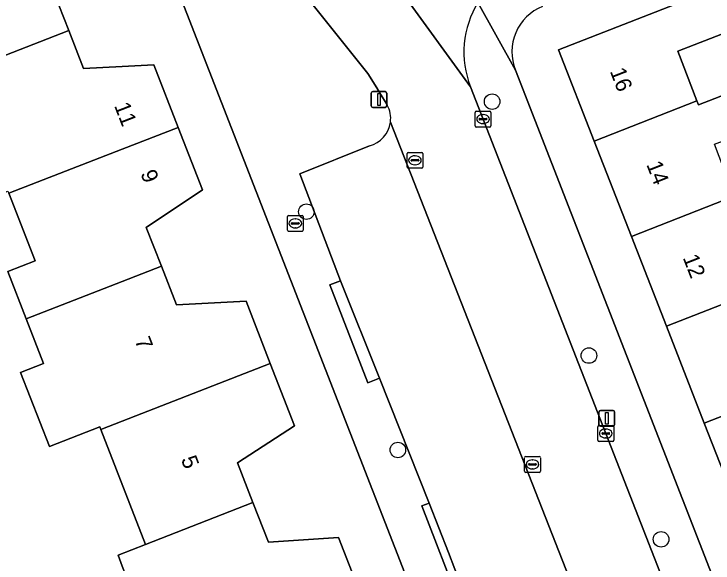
# Model space of a CAD drawing. Extents: x 159680 to 160786, y 387323 to 388340.
# Drawn here: x 159993.17 to 160037.27, y 387705.71 to 387740.35 of the extents above; entities that cross this region are included whole.
import ezdxf

# ---------------------------------------------------------------- set-up
doc = ezdxf.new("R2010")
doc.units = 0
for name, color, linetype in [('IMGEO_Boom', 7, 'Continuous'), ('IMGEO_Brandkraan', 7, 'Continuous'), ('IMGEO_Erf', 7, 'Continuous'), ('IMGEO_Kolk', 7, 'Continuous'), ('IMGEO_Lichtmast', 7, 'Continuous'), ('IMGEO_Pand', 7, 'Continuous'), ('IMGEO_Pand_nummerreeks', 7, 'Continuous'), ('IMGEO_Parkeervlak_open', 7, 'Continuous'), ('IMGEO_Rijbaan_lokaal_open', 7, 'Continuous'), ('IMGEO_Voetpad_open', 7, 'Continuous')]:
    doc.layers.add(name, color=color, linetype=linetype)

msp = doc.modelspace()

# ---------------------------------------------------------------- linework, layer by layer
at = {"layer": 'IMGEO_Boom'}
for centre in [(160023.329, 387734.817), (160011.613, 387727.875), (160029.436, 387718.799), (160017.386, 387712.847), (160033.988, 387707.208)]:
    msp.add_circle(centre, 0.489, dxfattribs=at)
at = {"layer": 'IMGEO_Brandkraan'}
for p, q in [((160010.413, 387726.709), (160010.413, 387727.561)), ((160010.488, 387727.635), (160011.34, 387727.635)), ((160010.901, 387727.415), (160010.926, 387727.415)), ((160011.414, 387727.561), (160011.414, 387726.709)), ((160010.672, 387727.129), (160010.672, 387727.141)), ((160011.11, 387727.092), (160010.712, 387727.092)), ((160010.715, 387727.178), (160011.113, 387727.178)), ((160010.924, 387726.855), (160010.899, 387726.855)), ((160011.156, 387727.141), (160011.156, 387727.129)), ((160011.34, 387726.635), (160010.488, 387726.635))]:
    msp.add_line(p, q, dxfattribs=at)
for points in [[(160010.413, 387726.709), (160010.413, 387727.561)], [(160010.488, 387727.635), (160011.34, 387727.635)], [(160011.414, 387727.561), (160011.414, 387726.709)], [(160011.34, 387726.635), (160010.488, 387726.635)]]:
    msp.add_lwpolyline(points, dxfattribs=at)
for centre, radius, start, end in [((160010.49, 387727.559), 0.0765, 91.552, 178.448), ((160010.49, 387727.559), 0.0765, 91.552, 178.448), ((160011.338, 387727.559), 0.0765, 1.552, 88.448), ((160011.338, 387727.559), 0.0765, 1.552, 88.448), ((160010.712, 387727.138), 0.0403, 85.8775, 175.7526), ((160010.709, 387727.128), 0.0366, 178.938, 274.7102), ((160011.113, 387727.135), 0.043, 264.8664, 352.4533), ((160011.117, 387727.14), 0.0386, 1.7309, 96.639), ((160010.49, 387726.711), 0.0765, 181.552, 268.448), ((160010.49, 387726.711), 0.0765, 181.552, 268.448), ((160011.338, 387726.711), 0.0765, 271.552, 358.448), ((160011.338, 387726.711), 0.0765, 271.552, 358.448)]:
    msp.add_arc(centre, radius, start, end, dxfattribs=at)
for centre, major_axis, ratio, start_param, end_param in [((160010.9, 387727.135), (-0.387, 0.002), 0.722429, 4.712389, 7.853982), ((160010.925, 387727.135), (-0.39, 0.002), 0.717154, 1.570796, 4.712389)]:
    msp.add_ellipse(centre, major_axis=major_axis, ratio=ratio, start_param=start_param, end_param=end_param, dxfattribs=at)
at = {"layer": 'IMGEO_Erf'}
for points in [[(159995.682, 387741.712), (159996.618, 387739.305), (159997.553, 387736.899), (160000, 387737.032), (160001.989, 387737.141), (160003.523, 387733.195), (160005.056, 387729.25), (160001.515, 387726.886), (160002.466, 387724.44), (160003.416, 387721.997), (160007.807, 387722.232), (160009.336, 387718.298), (160010.865, 387714.366), (160007.272, 387712.031), (160008.244, 387709.529), (160009.217, 387707.026), (160013.649, 387707.319), (160015.175, 387703.392), (160016.701, 387699.467), (160013.143, 387696.999), (160014.138, 387694.441), (160020.94, 387697.092), (160000.318, 387750)], [(159975.76, 387748.314), (159998.986, 387688.539), (160005.599, 387691.121), (160004.381, 387694.254), (160006.104, 387694.923), (160004.437, 387699.21), (160002.643, 387703.826), (160000.921, 387703.156), (160000, 387705.525), (159999.732, 387706.214), (160001.454, 387706.885), (159998.637, 387714.132), (159998.573, 387714.296), (159995.401, 387713.06), (159993.584, 387717.732), (159995.036, 387718.296), (159993.938, 387721.12), (159992.779, 387724.102), (159994.501, 387724.772), (159992.842, 387729.037)], [(160038.953, 387708.82), (160036.716, 387714.544), (160034.331, 387720.644), (160032.112, 387726.319), (160029.764, 387732.326), (160027.515, 387738.08), (160044.3, 387744.642)], [(160024.811, 387736.808), (160043.442, 387688.944)]]:
    msp.add_lwpolyline(points, dxfattribs=at)
msp.add_lwpolyline([(160040.757, 387736.624), (160039.547, 387739.743), (160035.038, 387737.994), (160036.254, 387734.86), (160036.348, 387734.617), (160040.857, 387736.366)], close=True, dxfattribs=at)
msp.add_arc((160027.649, 387737.975), 3.068, 111.9227, 202.3641, dxfattribs=at)
at = {"layer": 'IMGEO_Kolk'}
for p, q in [((160022.256, 387733.29), (160022.256, 387734.142)), ((160022.331, 387734.216), (160023.183, 387734.216)), ((160022.744, 387733.996), (160022.769, 387733.996)), ((160023.257, 387734.142), (160023.257, 387733.29)), ((160022.515, 387733.71), (160022.515, 387733.722)), ((160022.953, 387733.673), (160022.555, 387733.673)), ((160022.558, 387733.759), (160022.956, 387733.759)), ((160022.999, 387733.722), (160022.999, 387733.71)), ((160023.183, 387733.216), (160022.331, 387733.216)), ((160022.767, 387733.436), (160022.742, 387733.436)), ((160017.962, 387730.692), (160017.962, 387731.544)), ((160018.037, 387731.618), (160018.889, 387731.618)), ((160018.45, 387731.398), (160018.475, 387731.398)), ((160018.963, 387731.544), (160018.963, 387730.692)), ((160018.221, 387731.112), (160018.221, 387731.124)), ((160018.659, 387731.075), (160018.261, 387731.075)), ((160018.264, 387731.161), (160018.662, 387731.161)), ((160018.473, 387730.838), (160018.448, 387730.838)), ((160018.705, 387731.124), (160018.705, 387731.112)), ((160018.889, 387730.618), (160018.037, 387730.618)), ((160030, 387713.457), (160030, 387714.309)), ((160030.075, 387714.383), (160030.927, 387714.383)), ((160030.488, 387714.163), (160030.513, 387714.163)), ((160031.001, 387714.309), (160031.001, 387713.457)), ((160030.259, 387713.877), (160030.259, 387713.889)), ((160030.697, 387713.84), (160030.299, 387713.84)), ((160030.302, 387713.926), (160030.7, 387713.926)), ((160030.743, 387713.889), (160030.743, 387713.877)), ((160030.927, 387713.383), (160030.075, 387713.383)), ((160030.511, 387713.603), (160030.486, 387713.603)), ((160025.376, 387711.507), (160025.376, 387712.359)), ((160025.451, 387712.433), (160026.303, 387712.433)), ((160026.377, 387712.359), (160026.377, 387711.507)), ((160025.635, 387711.927), (160025.635, 387711.939)), ((160026.073, 387711.89), (160025.675, 387711.89)), ((160025.678, 387711.976), (160026.076, 387711.976)), ((160025.864, 387712.213), (160025.889, 387712.213)), ((160026.119, 387711.939), (160026.119, 387711.927)), ((160026.303, 387711.433), (160025.451, 387711.433)), ((160025.887, 387711.653), (160025.862, 387711.653))]:
    msp.add_line(p, q, dxfattribs=at)
for points in [[(160022.256, 387733.29), (160022.256, 387734.142)], [(160022.331, 387734.216), (160023.183, 387734.216)], [(160023.257, 387734.142), (160023.257, 387733.29)], [(160023.183, 387733.216), (160022.331, 387733.216)], [(160017.962, 387730.692), (160017.962, 387731.544)], [(160018.037, 387731.618), (160018.889, 387731.618)], [(160018.963, 387731.544), (160018.963, 387730.692)], [(160018.889, 387730.618), (160018.037, 387730.618)], [(160030, 387713.457), (160030, 387714.309)], [(160030.075, 387714.383), (160030.927, 387714.383)], [(160031.001, 387714.309), (160031.001, 387713.457)], [(160030.927, 387713.383), (160030.075, 387713.383)], [(160025.376, 387711.507), (160025.376, 387712.359)], [(160025.451, 387712.433), (160026.303, 387712.433)], [(160026.377, 387712.359), (160026.377, 387711.507)], [(160026.303, 387711.433), (160025.451, 387711.433)]]:
    msp.add_lwpolyline(points, dxfattribs=at)
for centre, radius, start, end in [((160022.333, 387734.14), 0.0765, 91.552, 178.448), ((160022.333, 387734.14), 0.0765, 91.552, 178.448), ((160023.181, 387734.14), 0.0765, 1.552, 88.448), ((160023.181, 387734.14), 0.0765, 1.552, 88.448), ((160022.555, 387733.719), 0.0403, 85.8775, 175.7526), ((160022.552, 387733.709), 0.0366, 178.938, 274.7102), ((160022.956, 387733.716), 0.043, 264.8664, 352.4533), ((160022.96, 387733.721), 0.0386, 1.7309, 96.639), ((160022.333, 387733.292), 0.0765, 181.552, 268.448), ((160022.333, 387733.292), 0.0765, 181.552, 268.448), ((160023.181, 387733.292), 0.0765, 271.552, 358.448), ((160023.181, 387733.292), 0.0765, 271.552, 358.448), ((160018.039, 387731.542), 0.0765, 91.552, 178.448), ((160018.039, 387731.542), 0.0765, 91.552, 178.448), ((160018.887, 387731.542), 0.0765, 1.552, 88.448), ((160018.887, 387731.542), 0.0765, 1.552, 88.448), ((160018.261, 387731.121), 0.0403, 85.8775, 175.7526), ((160018.258, 387731.111), 0.0366, 178.938, 274.7102), ((160018.662, 387731.118), 0.043, 264.8664, 352.4533), ((160018.666, 387731.123), 0.0386, 1.7309, 96.639), ((160018.039, 387730.694), 0.0765, 181.552, 268.448), ((160018.039, 387730.694), 0.0765, 181.552, 268.448), ((160018.887, 387730.694), 0.0765, 271.552, 358.448), ((160018.887, 387730.694), 0.0765, 271.552, 358.448), ((160030.077, 387714.307), 0.0765, 91.552, 178.448), ((160030.077, 387714.307), 0.0765, 91.552, 178.448), ((160030.925, 387714.307), 0.0765, 1.552, 88.448), ((160030.925, 387714.307), 0.0765, 1.552, 88.448), ((160030.299, 387713.886), 0.0403, 85.8775, 175.7526), ((160030.296, 387713.876), 0.0366, 178.938, 274.7102), ((160030.7, 387713.883), 0.043, 264.8664, 352.4533), ((160030.704, 387713.888), 0.0386, 1.7309, 96.639), ((160030.077, 387713.459), 0.0765, 181.552, 268.448), ((160030.077, 387713.459), 0.0765, 181.552, 268.448), ((160030.925, 387713.459), 0.0765, 271.552, 358.448), ((160030.925, 387713.459), 0.0765, 271.552, 358.448), ((160025.453, 387712.357), 0.0765, 91.552, 178.448), ((160025.453, 387712.357), 0.0765, 91.552, 178.448), ((160026.301, 387712.357), 0.0765, 1.552, 88.448), ((160026.301, 387712.357), 0.0765, 1.552, 88.448), ((160025.675, 387711.936), 0.0403, 85.8775, 175.7526), ((160025.672, 387711.926), 0.0366, 178.938, 274.7102), ((160026.076, 387711.933), 0.043, 264.8664, 352.4533), ((160026.08, 387711.938), 0.0386, 1.7309, 96.639), ((160025.453, 387711.509), 0.0765, 181.552, 268.448), ((160025.453, 387711.509), 0.0765, 181.552, 268.448), ((160026.301, 387711.509), 0.0765, 271.552, 358.448), ((160026.301, 387711.509), 0.0765, 271.552, 358.448)]:
    msp.add_arc(centre, radius, start, end, dxfattribs=at)
for centre, major_axis, ratio, start_param, end_param in [((160022.743, 387733.716), (-0.387, 0.002), 0.722429, 4.712389, 7.853982), ((160022.768, 387733.716), (-0.39, 0.002), 0.717154, 1.570796, 4.712389), ((160018.449, 387731.118), (-0.387, 0.002), 0.722429, 4.712389, 7.853982), ((160018.474, 387731.118), (-0.39, 0.002), 0.717154, 1.570796, 4.712389), ((160030.487, 387713.883), (-0.387, 0.002), 0.722429, 4.712389, 7.853982), ((160030.512, 387713.883), (-0.39, 0.002), 0.717154, 1.570796, 4.712389), ((160025.863, 387711.933), (-0.387, 0.002), 0.722429, 4.712389, 7.853982), ((160025.888, 387711.933), (-0.39, 0.002), 0.717154, 1.570796, 4.712389)]:
    msp.add_ellipse(centre, major_axis=major_axis, ratio=ratio, start_param=start_param, end_param=end_param, dxfattribs=at)
at = {"layer": 'IMGEO_Lichtmast'}
for p, q in [((160015.695, 387734.554), (160015.695, 387735.354)), ((160015.695, 387735.354), (160015.695, 387734.554)), ((160015.795, 387735.454), (160016.585, 387735.454)), ((160016.585, 387735.454), (160015.795, 387735.454)), ((160016.685, 387735.354), (160016.685, 387734.554)), ((160016.685, 387734.554), (160016.685, 387735.354)), ((160016.585, 387734.454), (160015.795, 387734.454)), ((160015.795, 387734.454), (160016.585, 387734.454)), ((160030.07, 387714.44), (160030.07, 387715.24)), ((160030.07, 387715.24), (160030.07, 387714.44)), ((160030.17, 387715.34), (160030.96, 387715.34)), ((160030.96, 387715.34), (160030.17, 387715.34)), ((160031.06, 387715.24), (160031.06, 387714.44)), ((160031.06, 387714.44), (160031.06, 387715.24)), ((160030.96, 387714.34), (160030.17, 387714.34)), ((160030.17, 387714.34), (160030.96, 387714.34))]:
    msp.add_line(p, q, dxfattribs=at)
for points in [[(160016.115, 387735.329), (160016.265, 387735.329), (160016.265, 387734.579), (160016.115, 387734.579), (160016.115, 387735.329)], [(160030.49, 387715.215), (160030.64, 387715.215), (160030.64, 387714.465), (160030.49, 387714.465), (160030.49, 387715.215)]]:
    msp.add_lwpolyline(points, dxfattribs=at)
for centre, start, end in [((160015.795, 387735.354), 90, 180), ((160015.795, 387735.354), 90, 180), ((160016.585, 387735.354), 0, 90), ((160016.585, 387735.354), 360, 90), ((160015.795, 387734.554), 180, 270), ((160015.795, 387734.554), 180, 270), ((160016.585, 387734.554), 270, 0), ((160016.585, 387734.554), 270, 0), ((160030.17, 387715.24), 90, 180), ((160030.17, 387715.24), 90, 180), ((160030.96, 387715.24), 0, 90), ((160030.96, 387715.24), 360, 90), ((160030.17, 387714.44), 180, 270), ((160030.17, 387714.44), 180, 270), ((160030.96, 387714.44), 270, 0), ((160030.96, 387714.44), 270, 0)]:
    msp.add_arc(centre, 0.1, start, end, dxfattribs=at)
at = {"layer": 'IMGEO_Pand'}
for points in [[(159999.229, 387744.189), (159997.708, 387748.102), (159987.045, 387743.95), (159987.004, 387744.054), (159981.993, 387742.106), (159984.024, 387736.881), (159987.314, 387738.16), (159988.086, 387736.175), (159988.151, 387736.008), (159996.618, 387739.305), (159995.682, 387741.712)], [(160046.55, 387738.886), (160044.3, 387744.642), (160027.515, 387738.08), (160029.764, 387732.326), (160036.254, 387734.86), (160035.038, 387737.994), (160039.547, 387739.743), (160040.757, 387736.624)], [(160001.989, 387737.141), (160000, 387737.032), (159997.553, 387736.899), (159996.618, 387739.305), (159988.151, 387736.008), (159988.086, 387736.175), (159986.209, 387735.446), (159989.189, 387727.78), (159992.787, 387729.178), (159992.842, 387729.037), (160000, 387731.824), (160003.523, 387733.195)], [(160040.757, 387736.624), (160040.857, 387736.366), (160036.348, 387734.617), (160036.254, 387734.86), (160029.764, 387732.326), (160032.112, 387726.319), (160038.589, 387728.848), (160037.36, 387732.135), (160041.869, 387733.821), (160043.071, 387730.603), (160048.898, 387732.879), (160046.55, 387738.886)], [(160003.523, 387733.195), (160000, 387731.824), (159992.842, 387729.037), (159994.501, 387724.772), (159992.779, 387724.102), (159993.938, 387721.12), (160000, 387723.48), (160002.466, 387724.44), (160001.515, 387726.886), (160005.056, 387729.25)], [(160032.112, 387726.319), (160034.331, 387720.644), (160040.854, 387723.191), (160039.642, 387726.278), (160044.139, 387728.043), (160045.352, 387724.953), (160051.117, 387727.204), (160048.898, 387732.879), (160043.071, 387730.603), (160043.128, 387730.452), (160038.589, 387728.848)], [(160043.229, 387717.087), (160041.962, 387720.394), (160046.457, 387722.115), (160047.71, 387718.842), (160053.501, 387721.103), (160051.117, 387727.204), (160045.352, 387724.953), (160045.482, 387724.623), (160040.985, 387722.858), (160040.854, 387723.191), (160034.331, 387720.644), (160036.716, 387714.544)], [(160007.807, 387722.232), (160003.416, 387721.997), (160002.466, 387724.44), (160000, 387723.48), (159993.938, 387721.12), (159995.036, 387718.296), (159993.584, 387717.732), (159995.401, 387713.06), (159998.573, 387714.296), (159998.637, 387714.132), (160000, 387714.663), (160009.336, 387718.298)], [(160036.716, 387714.544), (160038.953, 387708.82), (160045.504, 387711.378), (160044.265, 387714.539), (160048.719, 387716.285), (160049.959, 387713.123), (160055.739, 387715.38), (160053.501, 387721.103), (160047.71, 387718.842), (160043.229, 387717.087)], [(160009.336, 387718.298), (160000, 387714.663), (159998.637, 387714.132), (160001.454, 387706.885), (160008.244, 387709.529), (160007.272, 387712.031), (160010.865, 387714.366)], [(160008.244, 387709.529), (160001.454, 387706.885), (159999.732, 387706.214), (160000, 387705.525), (160000.921, 387703.156), (160002.643, 387703.826), (160004.437, 387699.21), (160015.175, 387703.392), (160013.649, 387707.319), (160009.217, 387707.026)]]:
    msp.add_lwpolyline(points, close=True, dxfattribs=at)
at = {"layer": 'IMGEO_Parkeervlak_open'}
for points in [[(160028.819, 387703.181), (160016.916, 387733.521)], [(160015.59, 387732.032), (160011.193, 387730.259), (160013.761, 387723.511), (160016.218, 387717.369), (160019.367, 387709.498), (160020.568, 387706.378), (160021.776, 387703.229), (160022.38, 387701.656), (160026.873, 387703.385)]]:
    msp.add_lwpolyline(points, dxfattribs=at)
msp.add_arc((160015.154, 387733.755), 1.777, 284.1895, 352.4384, dxfattribs=at)
at = {"layer": 'IMGEO_Rijbaan_lokaal_open'}
for points in [[(160021.961, 387735.751), (160013.336, 387747.64), (160008.53, 387745.755), (160008.762, 387745.396), (160011.619, 387741.451), (160015.485, 387736.6), (160016.05, 387735.681), (160016.293, 387735.286), (160016.681, 387734.654), (160016.715, 387734.598)], [(160013.336, 387747.64), (160021.961, 387735.751)], [(160029.51, 387702.449), (160034.24, 387704.299), (160021.961, 387735.751)], [(160016.916, 387733.521), (160028.819, 387703.181)]]:
    msp.add_lwpolyline(points, dxfattribs=at)
for centre, radius, start, end in [((160027.56, 387737.937), 6.01, 148.4674, 201.324), ((160015.145, 387733.748), 1.786, 352.7081, 28.4348)]:
    msp.add_arc(centre, radius, start, end, dxfattribs=at)
at = {"layer": 'IMGEO_Voetpad_open'}
for points in [[(160000.318, 387750), (160020.94, 387697.092), (160021.461, 387695.756), (160027.934, 387698.27), (160029.18, 387695.062), (160031.513, 387689.139), (160033.94, 387682.976), (160034.971, 387680.356), (160036.074, 387677.556), (160037.17, 387674.748), (160039.479, 387669.024)], [(160016.715, 387734.598), (160016.681, 387734.654), (160016.293, 387735.286), (160016.05, 387735.681), (160015.485, 387736.6), (160011.619, 387741.451)], [(160043.442, 387688.944), (160024.811, 387736.808), (160022.437, 387741.08)], [(160022.437, 387741.08), (160024.811, 387736.808)], [(160021.961, 387735.751), (160034.24, 387704.299), (160035.472, 387701.152), (160040.216, 387689.036), (160041.193, 387689.419), (160042.373, 387686.406), (160042.561, 387685.927), (160041.583, 387685.544), (160046.561, 387672.828)], [(160026.873, 387703.385), (160022.38, 387701.656), (160021.776, 387703.229), (160021.31, 387703.052), (160018.9, 387709.321), (160019.367, 387709.498), (160016.218, 387717.369), (160015.484, 387717.085), (160013.094, 387723.253), (160013.761, 387723.511), (160011.193, 387730.259), (160015.59, 387732.032)]]:
    msp.add_lwpolyline(points, dxfattribs=at)
for points in [[(160013.761, 387723.511), (160013.094, 387723.253), (160015.484, 387717.085), (160016.218, 387717.369)], [(160019.367, 387709.498), (160018.9, 387709.321), (160021.31, 387703.052), (160021.776, 387703.229), (160020.568, 387706.378)]]:
    msp.add_lwpolyline(points, close=True, dxfattribs=at)
for centre, radius, start, end in [((160027.56, 387737.937), 6.01, 148.4674, 201.324), ((160027.649, 387737.975), 3.068, 111.9227, 202.3641), ((160015.145, 387733.748), 1.786, 352.7081, 28.4348), ((160015.154, 387733.755), 1.777, 284.1895, 352.4384)]:
    msp.add_arc(centre, radius, start, end, dxfattribs=at)

# ---------------------------------------------------------------- texts
at = {"layer": 'IMGEO_Pand_nummerreeks'}
for s, rotation, p in [('16', 291.3512, (160030.745, 387736.739)), ('11', 291.2336, (159999.474, 387734.561)), ('14', 291.3512, (160033.046, 387730.854)), ('9', 291.2508, (160001.133, 387730.291)), ('12', 291.3512, (160035.346, 387724.972)), ('7', 291.2623, (160000.768, 387719.757)), ('5', 291.2623, (160003.686, 387712.257))]:
    msp.add_text(s, height=1, rotation=rotation, dxfattribs=at).set_placement(p)

doc.saveas('drawing.dxf')
